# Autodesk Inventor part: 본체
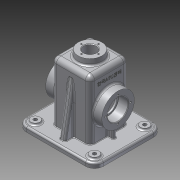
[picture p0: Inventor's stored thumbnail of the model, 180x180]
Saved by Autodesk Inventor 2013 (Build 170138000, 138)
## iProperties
Created: 2016-01
Part Number: 본체
Material: 알루미늄 6061
Document SubType Name: Modeling
Designer: User
Density: 1 g/cm^3
Mass: 298.56 g
Surface Area: 910.359 cm^2
Volume: 298.56 cm^3
Author: User
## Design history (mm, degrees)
sketch "스케치1"
  geometry: L1 (-32.5, 55)-(-32.5, -55); L2 (-32.5, -55)-(32.5, -55); L3 (32.5, -55)-(32.5, 55); L4 (32.5, 55)-(-32.5, 55); 3 further points
  constraints: 8 end point, 2 midpoint, 2 vertical, 1 horizontal alignment, 1 parallel, 1 perpendicular, 1 vertical alignment
  dimensions: "d0" = 110 distance of L1.start L1.end; "d1" = 65 distance of L1.end L2.end
extrude "돌출1" new body sketch "스케치1" stored distance "d2" = 65; taper "d3" = 0 deg
sketch "스케치2"
  geometry: L1 (65, -65)-(65, 0) reference; L2 (0, 0)-(65, 0) reference; L3 (0, -65)-(0, 0) reference; L4 (65, -65)-(0, -65) reference; L5 (-32.5, 25)-(97.5, 25); L6 (97.5, 25)-(97.5, -90); L7 (97.5, -90)-(-32.5, -90); L8 (-32.5, -90)-(-32.5, 25); 3 further points
  constraints: 8 end point, 2 midpoint, 2 parallel, 1 horizontal, 1 horizontal alignment, 1 perpendicular, 1 vertical alignment
  dimensions: "d4" = 130 distance of L6.end L7.end; "d5" = 115 distance of L5.end L6.end
extrude "돌출2" join sketch "스케치2" distance "d6" = 10; taper "d7" = 0 deg
sketch "스케치3"
  geometry: L1 (37.5, -30)-(92.5, -30); L2 (92.5, -30)-(92.5, -85); L3 (92.5, -85)-(37.5, -85); L4 (37.5, -85)-(37.5, -30); 3 further points
  constraints: 8 end point, 2 midpoint, 2 parallel, 1 horizontal, 1 horizontal alignment, 1 perpendicular, 1 vertical alignment
  dimensions: "d8" = 55 distance of L2.end L3.end; "d9" = 55 distance of L1.end L2.end
extrude "돌출3" cut sketch "스케치3" distance "d10" = 105; taper "d11" = 0 deg
sketch "스케치4"
  geometry: L1 (-25, -110)-(90, -110) reference; C1 r 27.5 at (32.5, -55); 1 further point
  constraints: 1 centre point, 1 coincident
  dimensions: "d12" = 27.5 radius of C1; "d13" = 55 distance from line of L1 C1.centre
extrude "돌출4" join sketch "스케치4" distance "d14" = 15; taper "d15" = 0 deg
hole "구멍1" diameter "d18" = 35; stored, may be unused: countersink angle "d22" = 90 deg, drill point angle "d24" = 0 deg; dims "d16" = 10, "d17" = 10, "d19" = 6, "d20" = 4, "d21" = 2, "d23" = 17
hole "구멍3" diameter "d36" = 30; stored, may be unused: countersink angle "d40" = 90 deg, drill point angle "d42" = 0 deg; dims "d34" = 10, "d35" = 10, "d37" = 6, "d38" = 4, "d39" = 2, "d41" = 17
sketch "스케치5"
  geometry: C1 r 20 at (32.5, 32.5); 1 further point
  constraints: 1 centre point, 1 coincident
  dimensions: "d43" = 20 radius of C1
extrude "돌출5" join sketch "스케치5" distance "d44" = 10; taper "d45" = 0 deg
hole "구멍4" diameter "d48" = 21; stored, may be unused: countersink angle "d52" = 90 deg, drill point angle "d54" = 0 deg; dims "d46" = 10, "d47" = 10, "d49" = 6, "d50" = 4, "d51" = 2, "d53" = 17
fillet "모깎기1" dims "d55" = 15
sketch "스케치6"
  geometry: C1 r 7.5 at (-17.5, 75); C2 r 7.5 at (-17.5, -10); A1 r 15 centre (-17.5, 75) between (-17.5, 90) and (-32.5, 75) reference; A2 r 15 centre (-17.5, -10) between (-32.5, -10) and (-17.5, -25) reference; 1 further point
  constraints: 2 centre point, 2 coincident
  dimensions: "d56" = 7.5 radius of C1; "d57" = 7.5 radius of C2
extrude "돌출6" join sketch "스케치6" distance "d58" = 3; taper "d59" = 0 deg
hole "구멍5" diameter "d62" = 6; stored, may be unused: countersink angle "d66" = 90 deg, drill point angle "d68" = 0 deg; dims "d60" = 10, "d61" = 10, "d63" = 6, "d64" = 4, "d65" = 2, "d67" = 17
hole "구멍6" diameter "d71" = 6; stored, may be unused: countersink angle "d75" = 90 deg, drill point angle "d77" = 0 deg; dims "d69" = 10, "d70" = 10, "d72" = 6, "d73" = 4, "d74" = 2, "d76" = 17
sketch "스케치7"
  geometry: L1 (100, 0)-(0, 0) reference; L2 (115, 100)-(115, 15) reference; L3 (0, 115)-(100, 115) reference; L4 (-15, 15)-(-15, 100) reference; L5 (110, 100)-(110, 15); L6 (100, 5)-(0, 5); L7 (-10, 15)-(-10, 100); L8 (0, 110)-(100, 110); A1 r 15 centre (0, 15) between (-15, 15) and (0, 0) reference; A2 r 15 centre (100, 15) between (100, 0) and (115, 15) reference; A3 r 15 centre (100, 100) between (115, 100) and (100, 115) reference; A4 r 15 centre (0, 100) between (0, 115) and (-15, 100) reference; A5 r 10 centre (100, 100) between (110, 100) and (100, 110); A6 r 10 centre (100, 15) between (100, 5) and (110, 15); A7 r 10 centre (0, 15) between (-10, 15) and (0, 5); A8 r 10 centre (0, 100) between (0, 110) and (-10, 100); 1 further point
  constraints: 8 end point, 8 point on circle, 4 centre point, 7 other
  dimensions: "d78" = 5 distance between parallel lines of L8 L3
extrude "돌출7" cut sketch "스케치7" distance "d79" = 2; taper "d80" = 0 deg
sketch "스케치8"
  geometry: L1 (-45, -47.5)-(40.069, -32.5); L2 (-45, -32.5)-(55, -32.5) reference; L3 (-45, -35)-(-45, -50) reference; L4 (-45, -42.5)-(-45, -57.5) reference; L5 (55, 32.5)-(-45, 32.5) reference; L6 (-45, 50)-(-45, 35) reference; L7 (-45, 57.5)-(-45, 42.5) reference; 1 further point
  constraints: 2 end point, 2 point on line
  dimensions: "d82" = 10 deg angle of L2 L1; "d83" = 10 distance of L4.end L1.start
feature "리브1" sketch "스케치8" dims "d84" = 1, "d85" = 10, "d86" = 0, "d87" = 0, "d88" = 1, "d89" = 1
sketch "스케치9"
  geometry: L1 (42.5, -27.5)-(42.5, -45); L2 (32.5, -27.5)-(47.5, -27.5) reference; L3 (50, -45)-(-50, -45) reference; L4 (27.5, -55)-(27.5, 50) reference; 1 further point
  constraints: 2 end point, 2 point on line, 1 vertical
  dimensions: "d90" = 15 distance between parallel lines of L1 L4
feature "리브2" sketch "스케치9" dims "d91" = 1, "d92" = 6, "d93" = 0, "d94" = 0, "d95" = 1, "d96" = 1
sketch "스케치10"
  geometry: C1 r 17.5 at (0, 0) reference; 1 further point
  constraints: 1 vertical alignment
  dimensions: "d97" = 21 distance of C1.centre point (0, 21)
hole "구멍7" sketch "스케치10" at (0, 21) diameter "d98" = 3.242; stored, may be unused: countersink angle "d102" = 90 deg, drill point angle "d104" = 118 deg; dims "d99" = 8, "d100" = 4, "d101" = 2, "d103" = 10
sketch "스케치11"
  geometry: C1 r 20 at (0, 0) reference; 1 further point
  constraints: 1 vertical alignment
  dimensions: "d108" = 14.5 distance of C1.centre point (0, 14.5)
hole "구멍8" sketch "스케치11" at (0, 14.5) diameter "d109" = 2.459; stored, may be unused: countersink angle "d113" = 90 deg, drill point angle "d115" = 118 deg; dims "d110" = 7, "d111" = 4, "d112" = 2, "d114" = 9
fillet "모깎기2" dims "d119" = 8
fillet "모깎기3" dims "d120" = 0.3
fillet "모깎기4" dims "d121" = 3
fillet "모깎기5" dims "d122" = 3
fillet "모깎기8" dims "d125" = 3
sketch "스케치12"
  geometry: L1 (-8, 0)-(-8, -92) reference; L2 (44.5, 18)-(4.5, 18) reference; 2 further points
  constraints: 1 other
  dimensions: "d127" = 32.5 distance from line of point (24.5, -8) L1; "d128" = 26 distance from line of L2 point (24.5, -8)
feature "엠보싱1" sketch "스케치12" dims "d6" = 10, "d129" = 0.5, "d130" = 0
fillet "모깎기10" dims "d131" = 3
fillet "모깎기11" dims "d132" = 3
fillet "모깎기12" dims "d133" = 3
fillet "모깎기13" dims "d134" = 1
chamfer "모따기1" distance "d135" = 1; stored, may be unused: second distance "d136" = 2, angle "d137" = 45 deg
feature "면 기울기1" dims angle "d138" = 5 deg
node "솔리드1"
mirror "대칭1"
mirror "대칭2"
mirror "대칭3"
mirror "대칭4"
pattern_circular "원형 패턴1" dims angle "d106" = 360 deg
mirror "대칭5"
pattern_circular "원형 패턴2" dims angle "d117" = 360 deg
